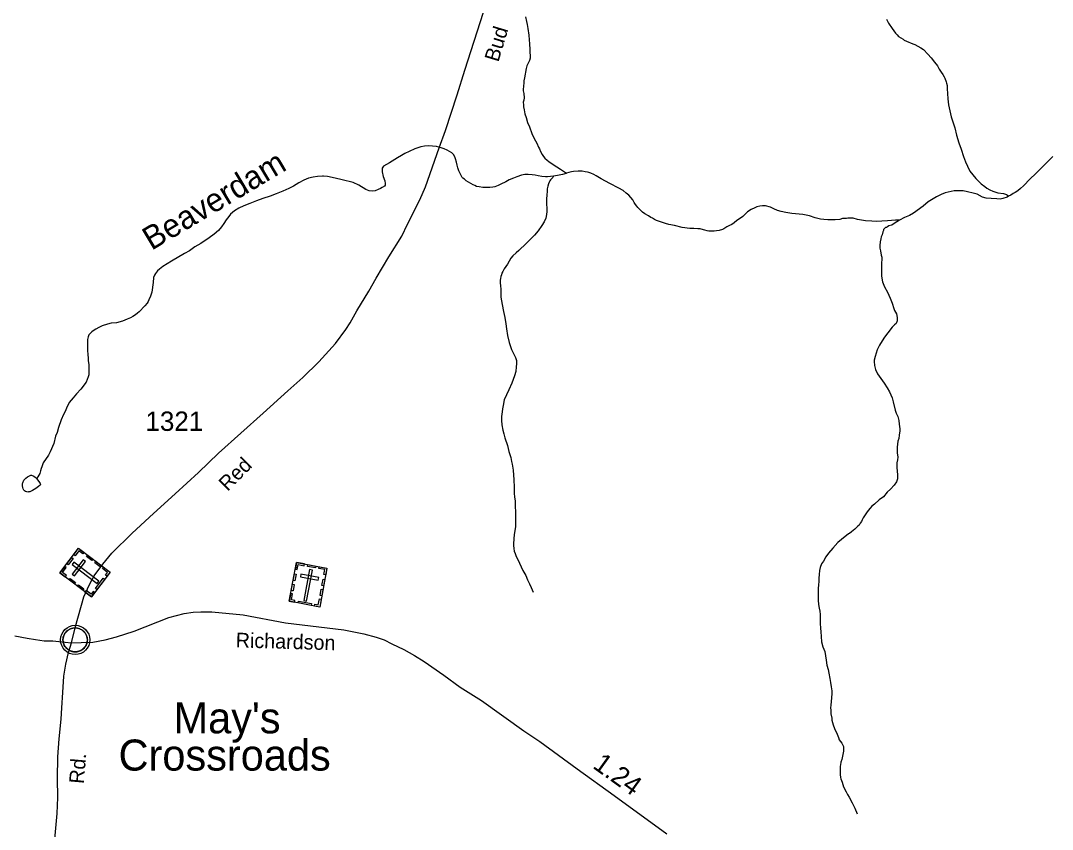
# Model space of a CAD drawing. Extents: x 2220236 to 2384410, y 720751 to 894131.
# Drawn here: x 2261721 to 2268370, y 826772 to 831987 of the extents above; entities that cross this region are included whole.
import ezdxf

# ---------------------------------------------------------------- set-up
doc = ezdxf.new("R2010")
doc.units = 0
doc.layers.add('Default', color=7, linetype='Continuous')

msp = doc.modelspace()

# ---------------------------------------------------------------- linework, layer by layer
at = {"layer": 'Default'}
for points in [[(2262048.7, 827976.2), (2262074.9, 828080.5), (2262127.4, 828272.8), (2262164.1, 828351.5), (2262195.6, 828408), (2262250.7, 828481.5), (2262309.7, 828552.3), (2262439.6, 828682), (2262576.4, 828809.3), (2262717, 828936.6), (2262867.8, 829073.4), (2262996.5, 829197.1), (2263284.2, 829456.6), (2263442.9, 829599.7), (2263538.7, 829685), (2263643.6, 829786), (2263749.2, 829905.5), (2263817.4, 829996), (2263844.9, 830038), (2263888.2, 830115.5), (2263964.3, 830241.5), (2264011.5, 830326.2), (2264094.2, 830464.8), (2264176.9, 830597.5), (2264214.1, 830673.9), (2264294.5, 830830.6), (2264329.9, 830914.8), (2264417.3, 831167.6), (2264458.4, 831277.9), (2264534.2, 831508.6), (2264582.6, 831667), (2264864, 832544.8)], [(2264975.1, 832010.8), (2264981.7, 831981.2), (2264985.9, 831961.4), (2264989.9, 831935.1), (2264996.3, 831893.3), (2264998.6, 831863.7), (2265000.7, 831837.4), (2265003.2, 831799.7), (2265003.1, 831781.6), (2265005.7, 831761.9), (2265003.7, 831745.5), (2264999.7, 831729.2), (2264994.2, 831716.9), (2264984, 831695.1), (2264978.3, 831677.2), (2264968.9, 831617.4), (2264964.9, 831598.7), (2264963.5, 831579.1), (2264961.4, 831570.9), (2264961.5, 831559.5)], [(2267300.3, 831996.4), (2267314.5, 831970.6), (2267336.8, 831936.6), (2267359.1, 831906.7), (2267370, 831895), (2267379.3, 831884.9), (2267407.5, 831867)], [(2267407.5, 831867), (2267415.6, 831861.2), (2267445.1, 831848.1), (2267455.6, 831844), (2267471.8, 831837.7), (2267483.8, 831831.9), (2267521.8, 831812.1), (2267538.6, 831799.6), (2267568.5, 831770.1), (2267588.7, 831746.8), (2267610.7, 831719.4), (2267629.3, 831695.1), (2267640.9, 831673.5), (2267653.3, 831653.6), (2267663.2, 831639.6), (2267673.7, 831623.6), (2267677.5, 831615.4), (2267685.2, 831593.2), (2267687.6, 831584), (2267691.2, 831567.5), (2267692.5, 831547.8), (2267694.4, 831516), (2267697, 831482.1), (2267701.1, 831443.7), (2267717.9, 831366.2), (2267728.4, 831333.9), (2267740.7, 831295.9), (2267753.2, 831248.1), (2267767.2, 831198.6), (2267781.8, 831158.3), (2267798.2, 831111), (2267810.6, 831076.3), (2267822.8, 831049.2), (2267839.2, 831016.7), (2267857.4, 830993.4), (2267877.6, 830969.3), (2267891.7, 830953.3), (2267912, 830934.2), (2267933.9, 830918), (2267948.1, 830906.2), (2267967.9, 830895.9), (2267986.1, 830886.7), (2268006.3, 830880.4), (2268018.4, 830876.9), (2268054.4, 830872.8), (2268074.2, 830865.2), (2268080.3, 830860.8), (2268088.4, 830854.1)], [(2264961.5, 831559.5), (2264959.6, 831547), (2264959.6, 831534.9), (2264963.9, 831516.8), (2264965.9, 831488.8), (2264964.3, 831474.8), (2264960.4, 831461.1), (2264960.7, 831444.7), (2264962.7, 831430.5), (2264966.9, 831410.8), (2264971, 831385.4), (2264979.3, 831361.3), (2264987.5, 831329.3), (2264999.7, 831301.2), (2265015.9, 831259.8), (2265030.6, 831225.8), (2265046.8, 831195.9), (2265059, 831172), (2265065, 831159.4), (2265071.6, 831142.3), (2265081.3, 831124), (2265090.2, 831110.7), (2265099.6, 831100.7), (2265113.4, 831086.3), (2265126, 831078.8), (2265139.9, 831068.7), (2265176.1, 831043.3), (2265200.1, 831028.7), (2265220.2, 831016.8), (2265232.4, 831007.7), (2265239.9, 831002.6)], [(2265155.2, 830983.1), (2265154.5, 830983.1), (2265136.4, 830980.8), (2265116.7, 830980.6), (2265102.6, 830979.9), (2265080.7, 830982), (2265056.5, 830985.8), (2265036.6, 830989.5), (2265016.6, 830993.2), (2264992.4, 830995.3), (2264970.4, 830995.1), (2264948.7, 830990.6), (2264919, 830980.4), (2264896.8, 830972), (2264869, 830960.1), (2264847.1, 830947.5), (2264815.3, 830931.7), (2264799.4, 830923.2), (2264777.2, 830915.5), (2264763.4, 830913.1), (2264743.7, 830911.2), (2264723.7, 830910.7), (2264699.7, 830910.5), (2264675.5, 830914.3), (2264659.2, 830917.9), (2264647.2, 830923.7), (2264637.4, 830928.2), (2264607.3, 830945.9), (2264593, 830953.7), (2264581.1, 830963.8), (2264571.1, 830971.2), (2264567.2, 830975.6), (2264556.8, 830992.9), (2264550.8, 831005.4), (2264544.5, 831019.3), (2264539, 831036.8), (2264534.5, 831055), (2264529.9, 831074.8), (2264523.8, 831095.2), (2264519.8, 831109.4), (2264511.6, 831122.7), (2264500.7, 831135.1), (2264469.2, 831152.1), (2264450.7, 831160), (2264431.1, 831166), (2264401.5, 831174.2), (2264375.3, 831178), (2264347.4, 831179.2), (2264323.1, 831177.4), (2264299.4, 831173), (2264261.1, 831160.7), (2264225.7, 831144), (2264195.9, 831129.9), (2264175.9, 831118.2), (2264150, 831101.3), (2264098.5, 831068.9), (2264060.4, 831049.1), (2264054.7, 831042.6), (2264050.6, 831034.5), (2264050.7, 831024.7), (2264050.7, 831010.9), (2264057, 830982.9), (2264067.2, 830953.1), (2264069.5, 830937.3), (2264069.6, 830926.8), (2264065.9, 830918.7), (2264051.9, 830910.8), (2264040, 830904.5), (2264025.8, 830898.2), (2264006.2, 830890.4), (2263988.2, 830888.2), (2263967.9, 830890.3), (2263946, 830897.3), (2263899.7, 830925.4), (2263863.7, 830943.2), (2263793.5, 830960.4), (2263747.2, 830971.9), (2263699.1, 830981.1), (2263673.3, 830984.9), (2263667.4, 830985), (2263633.2, 830980.8), (2263605.2, 830976.5), (2263575.6, 830970.5), (2263545.5, 830958), (2263513.7, 830941.6), (2263480.1, 830919.4), (2263449.9, 830903.6), (2263410.2, 830887), (2263368.5, 830870.9), (2263328.5, 830854.3), (2263281, 830839.9), (2263241, 830824.9), (2263197, 830807.2), (2263159.3, 830792.2), (2263127.2, 830778.1), (2263099.6, 830760), (2263073.9, 830739.8)], [(2268372.2, 831110), (2268308.6, 831047.3), (2268288.8, 831027.1), (2268261, 830999.1), (2268227.5, 830967), (2268184, 830922), (2268163.9, 830904.3), (2268148.2, 830889.9), (2268129.9, 830877.8), (2268118.3, 830871.5), (2268102.3, 830861.3), (2268088.4, 830854.1)], [(2267384, 830700.7), (2267374.1, 830700.9), (2267365.9, 830701.1), (2267364, 830701.2), (2267358.1, 830700.3), (2267334.4, 830698.5), (2267308.4, 830696.4), (2267270.3, 830693.9), (2267236.2, 830691.3), (2267206.4, 830693.6), (2267166.4, 830697), (2267114.4, 830704.7), (2267086.1, 830712.5), (2267052, 830714.2), (2267042.4, 830711.8), (2267018.4, 830710), (2267000.3, 830705.4), (2266970.1, 830703.4), (2266948.4, 830703.2), (2266922.2, 830702.8), (2266896.3, 830704.3), (2266876.4, 830706.3), (2266840.5, 830715.9), (2266804, 830727.5), (2266762.2, 830737.2), (2266690.2, 830743), (2266651.9, 830750.3), (2266621.9, 830755.9), (2266598.1, 830763.6), (2266575, 830773.3), (2266553.9, 830783.5), (2266521.6, 830793.1), (2266501.9, 830792.8), (2266485.8, 830790.5), (2266465.7, 830787), (2266451.8, 830780.7), (2266429.9, 830768.1), (2266406, 830753.8), (2266392.3, 830741.6), (2266374.2, 830724), (2266354.6, 830709.6), (2266336.6, 830697.8), (2266318.6, 830683.5), (2266304.9, 830672.9), (2266289, 830665), (2266273.1, 830657.2), (2266253.5, 830644.5), (2266243.3, 830640.7), (2266223.1, 830634.6), (2266205.4, 830632.3), (2266191.2, 830630.3), (2266171.2, 830629.8), (2266155.1, 830630.1), (2266145.3, 830631.9), (2266131.3, 830635.5), (2266121.2, 830639), (2266101.3, 830645.3), (2266085.3, 830644.7), (2266059.4, 830646.8), (2266033.1, 830646.7), (2265983.4, 830652.7), (2265935.1, 830665.8), (2265899.2, 830673.1), (2265877, 830679.5), (2265818.7, 830698.7), (2265807, 830704.5), (2265792.8, 830712.4), (2265782.7, 830718.2), (2265766.5, 830728.3), (2265744.5, 830741.9), (2265728.7, 830752.1), (2265698.4, 830781.6), (2265692, 830789.9), (2265684.1, 830801.6), (2265675.8, 830813.2), (2265665.7, 830831.5), (2265639.7, 830861.5), (2265623.3, 830875), (2265603.3, 830890.8), (2265577, 830906.1), (2265518.6, 830936.2), (2265461.5, 830966.9), (2265430.7, 830985.6), (2265414.5, 830994.8), (2265396.3, 831002.7), (2265382.3, 831006.9), (2265374.2, 831008.7), (2265358.5, 831012.3), (2265339.9, 831016), (2265326.4, 831016.3), (2265314.3, 831015.9), (2265284.4, 831013.9), (2265271.6, 831011.8), (2265254.4, 831007.9), (2265239.9, 831002.6)], [(2265155.2, 830983.1), (2265149.8, 830975), (2265146.7, 830970.8), (2265141, 830964.3), (2265136.7, 830960.5), (2265131.3, 830953.1), (2265126.8, 830944.3), (2265123.4, 830935.2), (2265119.4, 830920.5), (2265115.1, 830902.6), (2265113.5, 830888.8), (2265112, 830860), (2265109.9, 830840.4), (2265110.2, 830822.3), (2265110.4, 830800.3), (2265112.6, 830780.6), (2265112.7, 830756), (2265110.7, 830736.4), (2265105.3, 830712.5), (2265094, 830689.1), (2265080.7, 830666.5), (2265056, 830630.9), (2265032.2, 830603.5), (2265012.4, 830583.3), (2264978.6, 830548.9), (2264930.8, 830505.6), (2264915.4, 830490.1), (2264893, 830470.9), (2264880.2, 830454.8), (2264857.7, 830415.9), (2264838.1, 830386.1), (2264828.2, 830369.9), (2264822.4, 830359.2), (2264818.9, 830347.8), (2264816.4, 830337.4), (2264813.5, 830323.3), (2264811, 830313.5), (2264811, 830297.1), (2264813.2, 830277.4), (2264815.4, 830255.4), (2264815.5, 830229.8), (2264815.9, 830203.6), (2264824.2, 830157.5), (2264832.7, 830111.4), (2264841.1, 830071.8), (2264847.5, 830031.7), (2264851.7, 829999.5), (2264858, 829956), (2264868.6, 829912.2), (2264885, 829865.9), (2264901.4, 829832.1), (2264909.6, 829814.6), (2264915.7, 829794.8), (2264915.6, 829774.4), (2264914.2, 829754.8), (2264912.3, 829724.3), (2264903.2, 829696), (2264886.8, 829650.4), (2264866.5, 829605.5), (2264837.7, 829541.5), (2264830.7, 829504.6), (2264827.3, 829483.4), (2264824.6, 829465.4), (2264820.7, 829435.3), (2264819.2, 829409.7), (2264821.2, 829381.8), (2264827.7, 829345.6), (2264834.1, 829321.8), (2264842.1, 829297.7), (2264857.8, 829246.6), (2264867.2, 829208), (2264873, 829189.8), (2264879.2, 829170), (2264883.5, 829144.3), (2264887.8, 829127.9), (2264894.2, 829088.4), (2264896.5, 829056.5), (2264898.5, 829028.6), (2264901.1, 828976.1), (2264901.3, 828940), (2264903.4, 828914.3), (2264907.8, 828890.6), (2264908.1, 828856.2), (2264910.6, 828818.4), (2264910.9, 828787.9), (2264910.9, 828754.4), (2264909.3, 828724), (2264901.7, 828672.6), (2264896.2, 828616), (2264896.6, 828602.2), (2264898.5, 828584.1), (2264900.8, 828566.1), (2264907, 828551.8), (2264915.1, 828532), (2264925.2, 828512.1), (2264957.9, 828442.5), (2264976.2, 828408.7)], [(2265239.9, 831002.6), (2265236.2, 831001.7), (2265212.5, 830995), (2265180.6, 830989.1), (2265155.2, 830983.1)], [(2268088.4, 830854.1), (2268078.5, 830849.4), (2268050.4, 830839.5), (2268034.6, 830836.5), (2268012.6, 830838.6), (2267974.6, 830840), (2267942.5, 830841.7), (2267920.7, 830849.4), (2267886.3, 830867.5), (2267860.6, 830875.2), (2267822.3, 830882.6), (2267794.3, 830889), (2267778.2, 830890), (2267744.4, 830890.1), (2267738.2, 830888.6), (2267678.5, 830875.7), (2267652.4, 830865.7), (2267622.6, 830851.6), (2267602.7, 830838.9), (2267569.1, 830818.9), (2267537.4, 830790.1), (2267475.8, 830745.4), (2267449.9, 830731.2), (2267416.1, 830717.1), (2267384, 830700.7)], [(2263073.9, 830739.8), (2263062.1, 830723.7), (2263046.2, 830702), (2263030.3, 830677.8), (2263016.4, 830657.4), (2262996.6, 830633.2), (2262968.9, 830610.8), (2262935.3, 830586.3), (2262881.7, 830550.3), (2262843.8, 830527.5), (2262808.2, 830503.6), (2262776.4, 830485.2), (2262692.7, 830436.1), (2262637.2, 830402.2), (2262615.2, 830385.3), (2262603.2, 830373.4), (2262589.7, 830355.6), (2262583.6, 830344.9), (2262577.7, 830331.3), (2262576, 830297.5), (2262566.6, 830237), (2262558.8, 830209.3), (2262547.1, 830186.6), (2262543.3, 830176.8), (2262535.5, 830164.9), (2262521.4, 830148.7), (2262485.9, 830110.1), (2262473.9, 830100.5), (2262460.2, 830090), (2262443.9, 830078.2), (2262428.3, 830070.3), (2262408.1, 830061.6), (2262376.7, 830049.1), (2262338.8, 830039.4), (2262304.6, 830035.2), (2262280.5, 830030.7), (2262246.9, 830020), (2262225, 830007.9), (2262205.1, 829997.9), (2262189.1, 829987.4), (2262179.1, 829979.4), (2262169.4, 829969.7), (2262161.4, 829961.7), (2262155.5, 829947.1), (2262151.5, 829931.7), (2262151.9, 829915.3), (2262152, 829891.4), (2262152.1, 829877.6), (2262152.3, 829856.9), (2262154.5, 829837.2), (2262156.9, 829807.6), (2262156.9, 829795.5), (2262160.9, 829767.5), (2262161.4, 829741.3), (2262161.5, 829715.7), (2262159.6, 829703.6), (2262155.7, 829689.6), (2262144.2, 829655.4), (2262108.5, 829611.2), (2262081, 829580.6), (2262059.1, 829554.8), (2262033.6, 829524.2), (2262015.8, 829488.5), (2262008.1, 829466.3), (2261997.9, 829447.8), (2261982.4, 829412.1), (2261965, 829363.9), (2261955.4, 829331.3), (2261945.4, 829307.9), (2261933.9, 829259.6), (2261910.5, 829206.9), (2261900.6, 829184.8), (2261865.1, 829136.3), (2261857.4, 829110.3), (2261853.2, 829098.9), (2261849.6, 829084.2), (2261845.6, 829066.2), (2261831.7, 829044.5), (2261823, 829035.5)], [(2267384, 830700.7), (2267350.4, 830678.5), (2267334.8, 830669), (2267316.6, 830662.8), (2267306.7, 830658.1), (2267300.4, 830653.9), (2267294.4, 830652.4), (2267286.7, 830644.4), (2267282.7, 830639.5), (2267280.9, 830634), (2267276.8, 830624.2), (2267273.1, 830606.3), (2267267, 830593.9), (2267265.4, 830580.2), (2267259.7, 830559.7), (2267257.9, 830536.1), (2267257.9, 830519.7), (2267262.1, 830501.5), (2267266.4, 830473.6), (2267270.1, 830462), (2267270.6, 830453.8), (2267268.9, 830417.8), (2267269, 830375.8), (2267269.6, 830339.7), (2267275.7, 830301.8), (2267288.1, 830269.8), (2267306.5, 830236.6), (2267325, 830196.8), (2267337.1, 830166.1), (2267349.2, 830130.7), (2267353.5, 830118.2), (2267359.5, 830106.6), (2267365.6, 830096.6), (2267370, 830072.9), (2267369.8, 830050.6), (2267364.3, 830034.3), (2267352.3, 830024.7), (2267338.5, 830010.3), (2267308.9, 829974.1), (2267289, 829945.7), (2267273.4, 829921.4), (2267255.7, 829893.9), (2267242, 829864), (2267234, 829843.5), (2267228.3, 829821.6), (2267222.6, 829797.2), (2267220.8, 829789.7), (2267222.9, 829763.4), (2267231.2, 829737.9), (2267243.4, 829709.8), (2267265.4, 829679.8), (2267285.7, 829648.3), (2267306.2, 829620), (2267320.4, 829594.1), (2267338.6, 829554.3), (2267344.9, 829529), (2267357.3, 829474.6), (2267363.8, 829456.4), (2267373.8, 829434.9), (2267380.2, 829408.5), (2267382, 829384.5), (2267386.6, 829354.9), (2267386.3, 829342.8), (2267382.8, 829315), (2267381, 829292.7), (2267375.1, 829276.4), (2267371.4, 829256.8), (2267369.4, 829236.5), (2267369.7, 829222.4), (2267369.9, 829200.4), (2267374.3, 829172.5), (2267372.3, 829154.5), (2267368.6, 829134.9), (2267366.7, 829107), (2267369.1, 829080.7), (2267371, 829061), (2267371.4, 829033.1), (2267365.4, 829014.2), (2267349.9, 828990.9), (2267326.1, 828965.8), (2267306.3, 828945.9), (2267282.4, 828917.5), (2267252.8, 828897.8), (2267223, 828869.6), (2267207, 828856.8), (2267195.3, 828843.2), (2267183.5, 828828.7), (2267171.7, 828812.6), (2267159.8, 828793.1), (2267151.7, 828780.8), (2267143.9, 828768.9), (2267140, 828758.1), (2267131.9, 828746.2), (2267124.5, 828734.8), (2267114.4, 828724.2), (2267096.7, 828708.2), (2267076.6, 828689.9)], [(2261823, 829035.5), (2261824, 829033.9), (2261832, 829024.9), (2261842.8, 829009.9), (2261846.6, 829003.2), (2261848.1, 828997.3), (2261846.1, 828992.4), (2261836.4, 828983.8), (2261827.4, 828976.4), (2261818.7, 828970), (2261797.1, 828957.4), (2261780.9, 828949.5), (2261772.7, 828948), (2261766.8, 828947.5), (2261759.9, 828949.3), (2261752.7, 828951.7), (2261744.9, 828955.2), (2261741.4, 828959.5), (2261738.5, 828963.5), (2261736.7, 828967.8), (2261734.5, 828976), (2261732.5, 828987.6), (2261732.4, 828997.4), (2261733.1, 829002.3), (2261735.2, 829007.8), (2261742.1, 829023.4), (2261754.2, 829037.9), (2261765.8, 829045.9), (2261769.8, 829048.1), (2261777.8, 829052.2), (2261786.1, 829056), (2261792, 829055.9), (2261805.9, 829050), (2261813.7, 829043.9), (2261823, 829035.5)], [(2267076.6, 828689.9), (2267062.6, 828679.4), (2267056.7, 828677.9), (2267011, 828641.1), (2266987.3, 828622.9), (2266955.7, 828584.8), (2266928.2, 828552.6), (2266910.3, 828530), (2266894.7, 828502.5), (2266882.8, 828484), (2266872.8, 828461.9), (2266869.1, 828442.3), (2266867.3, 828416.1), (2266865.5, 828391.5), (2266864, 828370.2), (2266861.9, 828348.3), (2266860.2, 828326), (2266860, 828317.8), (2266860.2, 828294.2), (2266860.6, 828266.3), (2266860.9, 828249.9), (2266862.9, 828222), (2266867.4, 828199.6), (2266871.6, 828179.8), (2266873.7, 828157.8), (2266873.8, 828143.7), (2266874, 828124), (2266874.2, 828100.4), (2266876.2, 828069.9), (2266878.6, 828046.2), (2266879, 828015.7), (2266883.2, 827982.1), (2266891.7, 827949.8), (2266903.9, 827918.4), (2266908.2, 827892.1), (2266912.6, 827862.5), (2266916.5, 827832.2), (2266924.8, 827802.5), (2266929.2, 827780.1), (2266935.4, 827744.9), (2266939.4, 827718.6), (2266943.8, 827690.6), (2266948.2, 827666.6), (2266948.5, 827648.5), (2266946.6, 827620.7), (2266944.8, 827597.1), (2266943, 827572.6), (2266941, 827556.8), (2266941.3, 827540.4), (2266943.4, 827516.8), (2266947.8, 827490.5), (2266949.8, 827476.3), (2266958.1, 827446.6), (2266966.1, 827422.8), (2266982.4, 827387.1), (2266992.8, 827364.9), (2266995.1, 827350.7), (2267013, 827329), (2267023.4, 827307.5), (2267023.4, 827277.3), (2267017.9, 827245.3), (2267012.2, 827223.4), (2267006.5, 827205.5), (2267004.2, 827189.2), (2267002.7, 827179.4), (2267002.5, 827169.5), (2267002.7, 827147.2), (2267003.3, 827126.9), (2267005.2, 827107.1), (2267007.2, 827097.3), (2267015.7, 827077.4), (2267023.9, 827047.7), (2267040.3, 827013.6), (2267050.1, 826998), (2267060.2, 826979.7), (2267080.5, 826943.9), (2267096.8, 826910.1), (2267111.1, 826872.1)], [(2264976.2, 828408.7), (2264988.4, 828381.2), (2265000.7, 828354.7), (2265011, 828330.9), (2265023.5, 828301.1)], [(2262048.7, 827976.2), (2262111.3, 827978.1), (2262186.1, 827980.1), (2262266.7, 827993.9), (2262339.5, 828013.6), (2262451.7, 828051), (2262676, 828137.6), (2262774.3, 828165.2), (2262833.3, 828173), (2262882.5, 828175), (2262953.4, 828175), (2263154.3, 828154.9), (2263428.5, 828103.6), (2263804.9, 828059.2), (2263933.1, 828032.4), (2264011.2, 828011.1), (2264063.3, 827993.7), (2264113.5, 827968), (2264190, 827932.8), (2264260.1, 827893.4), (2264320.5, 827855.9), (2264447.3, 827767.3), (2264554, 827690.3), (2264690.8, 827603.7), (2264964.5, 827408.3), (2265067, 827339.4), (2265306.7, 827163.6), (2265546.1, 826991.9), (2265886.2, 826743.3)], [(2261683.4, 828019.5), (2261762.3, 828006), (2261816.3, 827996.5), (2261872.3, 827989), (2261928.3, 827987.6), (2261966.4, 827983.8), (2262048.7, 827976.2)], [(2261942.1, 826708.3), (2261955.9, 826875.7), (2261960.5, 826978.1), (2261959.5, 827100.1), (2261961.4, 827240.1), (2261968.2, 827356.1), (2261982.4, 827482), (2261986.4, 827556.8), (2261992.3, 827655.3), (2262000.1, 827759.6), (2262013.3, 827837), (2262029.7, 827913.2), (2262048.7, 827976.2)]]:
    msp.add_lwpolyline(points, dxfattribs=at)
for points in [[(2261974.2, 828426.1), (2262094.4, 828584.7), (2262297.4, 828431), (2262177.1, 828272.3)], [(2262129, 828558.6), (2262122.2, 828549.6), (2262096.5, 828569), (2262072, 828536.7), (2262063.1, 828543.4), (2262094.5, 828584.7)], [(2262018.9, 828485.1), (2262050.2, 828526.4), (2262059.3, 828519.5), (2262028, 828478.2)], [(2262063.4, 828495.2), (2262052.1, 828480.4), (2262213.7, 828357.9), (2262225, 828372.8)], [(2262053.1, 828417.5), (2262068, 828406.2), (2262139.1, 828500), (2262124.2, 828511.3)], [(2262180.4, 828505.4), (2262145.9, 828531.5), (2262152.7, 828540.6), (2262187.3, 828514.4)], [(2262232.9, 828465.5), (2262198.4, 828491.7), (2262205.3, 828500.8), (2262239.8, 828474.6)], [(2263499.4, 828493), (2263695.1, 828456.4), (2263648.2, 828206.1), (2263452.5, 828242.8)], [(2263491.4, 828450.5), (2263502.6, 828448.4), (2263508.5, 828480), (2263548.3, 828472.6), (2263550.4, 828483.5), (2263499.4, 828493)], [(2263572.2, 828479.4), (2263623.1, 828469.9), (2263621, 828458.7), (2263570.1, 828468.2)], [(2262008.7, 828399.9), (2262015.6, 828408.9), (2261989.9, 828428.4), (2262014.4, 828460.7), (2262005.5, 828467.4), (2261974.2, 828426.1)], [(2262277.4, 828404.6), (2262268.2, 828411.5), (2262281.5, 828429), (2262249.3, 828453.4), (2262256, 828462.3), (2262297.4, 828431)], [(2263477.7, 828377.6), (2263485.7, 828420.2), (2263496.9, 828418.1), (2263488.9, 828375.5)], [(2263527, 828418.6), (2263523.5, 828400.3), (2263639.3, 828378.6), (2263642.7, 828397)], [(2263601.1, 828444.2), (2263582.8, 828447.6), (2263545.5, 828248.3), (2263563.8, 828244.9)], [(2263687.2, 828413.8), (2263676, 828415.9), (2263681.9, 828447.5), (2263642, 828455), (2263644.1, 828465.9), (2263695.1, 828456.4)], [(2262067.8, 828355.1), (2262033.3, 828381.2), (2262040.2, 828390.3), (2262074.7, 828364.2)], [(2262121.4, 828314.5), (2262086.8, 828340.6), (2262093.7, 828349.7), (2262128.2, 828323.6)], [(2262202.7, 828325), (2262253.9, 828392.6), (2262263, 828385.8), (2262211.8, 828318.1)], [(2263465.4, 828311.5), (2263473.3, 828354.1), (2263484.5, 828352), (2263476.6, 828309.4)], [(2263662.5, 828344.1), (2263670.5, 828386.6), (2263681.7, 828384.5), (2263673.7, 828342)], [(2262197.1, 828298.7), (2262187.9, 828305.6), (2262174.6, 828288.1), (2262142.4, 828312.5), (2262135.7, 828303.6), (2262177.1, 828272.3)], [(2263485.1, 828236.7), (2263487.2, 828248), (2263465.5, 828252.1), (2263473, 828291.8), (2263462, 828293.8), (2263452.5, 828242.8)], [(2263650.3, 828279.3), (2263658.3, 828321.8), (2263669.5, 828319.7), (2263661.5, 828277.2)], [(2263511.1, 828243.5), (2263594.5, 828227.9), (2263592.4, 828216.7), (2263509, 828232.3)], [(2263615.7, 828212.2), (2263617.8, 828223.5), (2263639.4, 828219.5), (2263646.8, 828259.2), (2263657.8, 828257.2), (2263648.2, 828206.1)], [(2261994.9, 828006.6), (2261995.9, 828012.2), (2261997.6, 828018.7), (2262000.6, 828025.9), (2262003.5, 828031.7), (2262006.8, 828037.4), (2262010.6, 828042.5), (2262014.6, 828046.9), (2262019.1, 828051.5), (2262024.7, 828056.1), (2262030.1, 828059.7), (2262035, 828062.6), (2262040, 828065.1), (2262045.5, 828067.4), (2262051.1, 828069.2), (2262055.5, 828070.3), (2262060.3, 828071.1), (2262064.4, 828071.8), (2262070.8, 828072.1), (2262075.2, 828072), (2262080.9, 828071.7), (2262085.8, 828071), (2262090.7, 828070), (2262095.7, 828068.6), (2262100.9, 828066.6), (2262107.5, 828063.7), (2262113.8, 828060.2), (2262118.9, 828056.7), (2262124, 828052.6), (2262127.3, 828049.5), (2262131.5, 828045.1), (2262135.3, 828040.4), (2262138.4, 828035.8), (2262141.5, 828030.8), (2262144, 828025.7), (2262146, 828020.7), (2262147.6, 828015.7), (2262148.9, 828011.1), (2262150, 828005), (2262150.6, 828000.3), (2262150.8, 827994.3), (2262150.7, 827988.5), (2262150.1, 827982.8), (2262149.1, 827977.4), (2262147.5, 827971.2), (2262145.6, 827965.4), (2262143.3, 827960.3), (2262140.2, 827954.3), (2262136.9, 827949), (2262133.4, 827944.3), (2262129.2, 827939.5), (2262123.9, 827934.6), (2262118.9, 827930.4), (2262113.9, 827927), (2262109.6, 827924.5), (2262102.8, 827921.3), (2262095.6, 827918.5), (2262089.7, 827917.1), (2262083.1, 827915.8), (2262078.6, 827915.3), (2262074.1, 827915.1), (2262068.6, 827915.1), (2262064.3, 827915.5), (2262058.6, 827916.2), (2262052.7, 827917.5), (2262048.1, 827918.8), (2262043, 827920.7), (2262038.4, 827922.7), (2262034.5, 827924.9), (2262027.7, 827929), (2262022.1, 827933.3), (2262017.2, 827937.7), (2262012.7, 827942.6), (2262009.5, 827946.6), (2262006.5, 827950.7), (2262002.4, 827957.8), (2262000.7, 827961.4), (2261999, 827965.4), (2261996.4, 827973.6), (2261994.9, 827980.6), (2261994.2, 827985.8), (2261993.9, 827992.1), (2261993.8, 827996.8), (2261994.4, 828003.3)]]:
    msp.add_lwpolyline(points, close=True, dxfattribs=at)
for centre, radius in [((2262072.5, 827994.1), 94.3), ((2262072.2, 827994.4), 76.7)]:
    msp.add_circle(centre, radius, dxfattribs=at)

# ---------------------------------------------------------------- texts
for s, height, rotation, p in [('Bud', 95, 73.2599, (2264799.4, 831715.4)), ('Beaverdam', 150, 30.88882, (2262564.5, 830502.2)), ('Red', 95, 45.30713, (2263055, 828947.7)), ('Richardson', 95, 358.34161, (2263106.1, 827946)), ('Rd.', 95, 84.99989, (2262127.2, 827063.5)), ('1.24', 125, 324.35158, (2265401.4, 827172.6))]:
    msp.add_text(s, height=height, rotation=rotation, dxfattribs=at).set_placement(p)
for s, height, p in [('1321', 125, (2262525.7, 829341.6)), ("May's", 200, (2262706.3, 827391.6)), ('Crossroads', 200, (2262352, 827151.6))]:
    msp.add_text(s, height=height, dxfattribs=at).set_placement(p)

doc.saveas('drawing.dxf')
